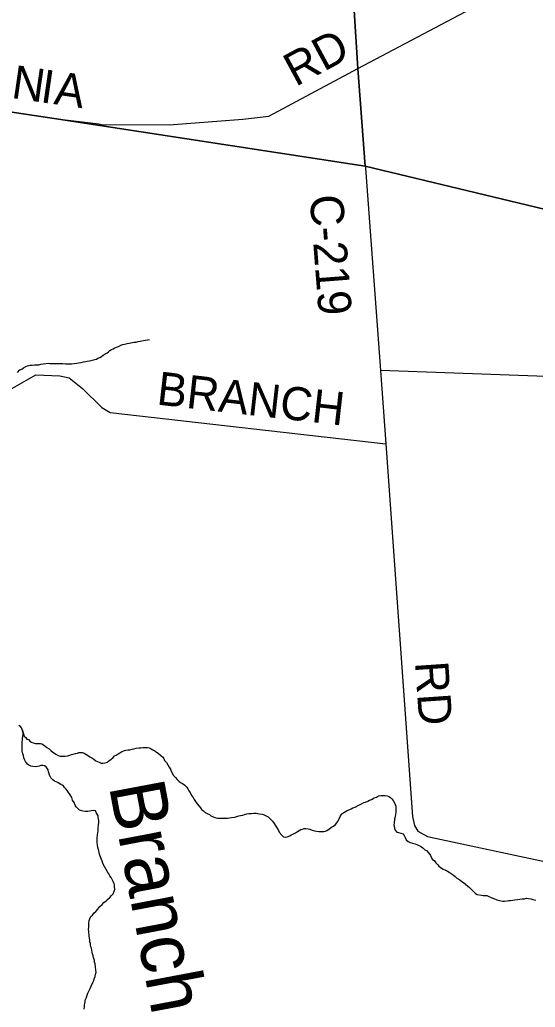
# Model space of a CAD drawing. Extents: x 0.4 to 34.4, y -2.1 to 19.9.
# Drawn here: x 4.522 to 5.402, y 15.102 to 16.79 of the extents above; entities that cross this region are included whole.
import ezdxf

# ---------------------------------------------------------------- set-up
doc = ezdxf.new("R2010")
doc.units = 0
for name, color, linetype in [('GM_X_County_Road', 7, 'Continuous'), ('GM_X_County_Road_Text', 7, 'Continuous'), ('GM_X_Minor_River', 7, 'Continuous'), ('GM_X_Minor_River_Text', 7, 'Continuous'), ('GM_X_Township', 7, 'Continuous'), ('GM_X_Township_Road', 7, 'Continuous')]:
    doc.layers.add(name, color=color, linetype=linetype)

msp = doc.modelspace()

# ---------------------------------------------------------------- linework, layer by layer
at = {"layer": 'GM_X_County_Road'}
for points in [[(5.0993, 16.7069), (5.2822, 16.8039), (5.7558, 17.055), (6.3625, 17.3767), (6.38, 17.386), (6.7247, 17.5708), (6.7542, 17.5855), (6.7786, 17.6112), (6.7991, 17.6537), (6.9135, 17.8219), (6.9221, 17.8335), (6.9343, 17.8393), (6.9503, 17.8402), (7.0217, 17.8445), (7.032, 17.8492), (7.2391, 18.0795)], [(4.6572, 16.6121), (4.6615, 16.6115), (4.7773, 16.6105), (4.9028, 16.6206), (4.9471, 16.6252), (5.0993, 16.7069)], [(5.0993, 16.7069), (5.1117, 16.5403), (5.112, 16.5365)], [(4.2994, 16.6582), (4.3075, 16.6628), (4.5805, 16.6217), (4.6572, 16.6121)], [(5.112, 16.5365), (5.1378, 16.1909), (5.1472, 16.0652)], [(4.0921, 16.025), (4.112, 16.0159), (4.1298, 16.0125), (4.1477, 16.0209), (4.1695, 16.03), (4.1937, 16.0409), (4.2276, 16.0516), (4.3098, 16.0801), (4.378, 16.119), (4.4038, 16.139), (4.4192, 16.1456), (4.4477, 16.1507), (4.4785, 16.1517), (4.5055, 16.158), (4.5496, 16.1834), (4.5902, 16.1818), (4.6065, 16.1781), (4.6289, 16.1599), (4.662, 16.1274), (4.6763, 16.1188), (5.1472, 16.0652)], [(5.1472, 16.0652), (5.1472, 16.0652), (5.1927, 15.4283), (5.1962, 15.413), (5.2017, 15.4034), (5.2182, 15.394), (5.4257, 15.3499), (5.4355, 15.3459), (5.4407, 15.3424), (5.4524, 15.2606), (5.4094, 15.0538), (5.3948, 14.9559)]]:
    msp.add_lwpolyline(points, dxfattribs=at)
at = {"layer": 'GM_X_Minor_River'}
for points in [[(4.6813, 16.2279), (4.6844, 16.2294), (4.6871, 16.2305), (4.6905, 16.232), (4.6944, 16.2338), (4.6978, 16.2352), (4.7009, 16.2359), (4.7055, 16.237), (4.7086, 16.2373), (4.7116, 16.238), (4.7143, 16.2384), (4.7174, 16.2391), (4.7208, 16.2394), (4.7239, 16.2401), (4.7277, 16.2408), (4.7304, 16.2415), (4.7335, 16.2422), (4.7361, 16.2425), (4.7403, 16.2432), (4.7434, 16.2435)], [(4.518, 16.1876), (4.5222, 16.1917), (4.5253, 16.1931), (4.5284, 16.1954), (4.5323, 16.1976), (4.5354, 16.199), (4.5396, 16.1997), (4.5434, 16.2), (4.5472, 16.2003), (4.551, 16.2006), (4.5545, 16.2006), (4.5579, 16.2013), (4.5621, 16.202), (4.5663, 16.2027), (4.5702, 16.203), (4.5728, 16.2029), (4.5763, 16.2028), (4.5793, 16.2028), (4.582, 16.2027), (4.5846, 16.2027), (4.5884, 16.2026), (4.593, 16.2025), (4.5957, 16.2025), (4.5999, 16.2024), (4.6033, 16.2024), (4.6071, 16.2023), (4.6106, 16.2022), (4.6148, 16.2029), (4.6193, 16.2032), (4.622, 16.2039), (4.6266, 16.2042), (4.6308, 16.2053), (4.6347, 16.206), (4.6373, 16.2067), (4.6412, 16.2074), (4.6454, 16.2084), (4.65, 16.2095), (4.6527, 16.2102), (4.6554, 16.2117), (4.6585, 16.2131), (4.6615, 16.2146), (4.6646, 16.2168), (4.6677, 16.2191), (4.6704, 16.2205), (4.6732, 16.2228), (4.6759, 16.225), (4.6786, 16.2265), (4.6813, 16.2279)], [(4.6839, 15.3082), (4.6836, 15.3109), (4.6829, 15.3135), (4.6815, 15.3174), (4.6793, 15.3216), (4.6778, 15.3243), (4.676, 15.327), (4.6741, 15.3301), (4.6723, 15.3328), (4.6693, 15.3378), (4.6671, 15.342), (4.6646, 15.347), (4.6624, 15.3523), (4.6603, 15.3577), (4.6592, 15.3604), (4.6581, 15.3638), (4.6574, 15.3669), (4.6564, 15.3719), (4.6553, 15.3753), (4.6546, 15.3791), (4.6544, 15.3837), (4.6541, 15.3879), (4.6542, 15.3921), (4.6546, 15.3966), (4.6551, 15.4008), (4.6556, 15.4035), (4.6556, 15.4061), (4.6561, 15.4088), (4.6565, 15.4137), (4.6567, 15.4187), (4.6567, 15.4213), (4.6561, 15.4267), (4.6558, 15.4293), (4.6543, 15.4324), (4.6525, 15.4355), (4.651, 15.4382), (4.6472, 15.4386), (4.6438, 15.4383), (4.6411, 15.4376), (4.638, 15.4369), (4.6342, 15.437), (4.6304, 15.4374), (4.6277, 15.4378), (4.624, 15.4394), (4.6206, 15.4429), (4.618, 15.4449), (4.6165, 15.4479), (4.6147, 15.4522), (4.6121, 15.4564), (4.6111, 15.4606), (4.6081, 15.4652), (4.6052, 15.4695), (4.6033, 15.4725), (4.6007, 15.4756), (4.5981, 15.478), (4.5959, 15.4814), (4.5921, 15.483), (4.5895, 15.4846), (4.5869, 15.4865), (4.5839, 15.4877), (4.5812, 15.4885), (4.5782, 15.4909), (4.5752, 15.4944), (4.5734, 15.4978), (4.572, 15.5013), (4.5713, 15.5047), (4.5702, 15.5082), (4.5669, 15.5135), (4.5643, 15.5151), (4.5612, 15.5155), (4.5578, 15.5156), (4.5551, 15.5145), (4.5524, 15.5138), (4.5486, 15.5131), (4.544, 15.5136), (4.541, 15.5144), (4.5376, 15.516), (4.535, 15.5179), (4.5316, 15.5222), (4.5305, 15.5249), (4.5291, 15.5287), (4.5281, 15.5329), (4.5274, 15.5356), (4.5263, 15.5405), (4.526, 15.5432), (4.5261, 15.5466), (4.5258, 15.5516), (4.5263, 15.5561), (4.5264, 15.5588), (4.5268, 15.5615), (4.5272, 15.5649), (4.5277, 15.5679), (4.5278, 15.5706), (4.5274, 15.5732), (4.526, 15.5771), (4.5249, 15.5798), (4.5231, 15.5825), (4.5204, 15.584)], [(4.526, 15.5771), (4.5292, 15.5656), (4.5322, 15.5633), (4.534, 15.5606), (4.5367, 15.5598), (4.5393, 15.5574), (4.5419, 15.5555), (4.5449, 15.5543), (4.5487, 15.5534), (4.5529, 15.553), (4.5571, 15.5529), (4.5598, 15.5525), (4.5624, 15.5509), (4.565, 15.5493), (4.5684, 15.5466), (4.5722, 15.5439), (4.5748, 15.5412), (4.5785, 15.5384), (4.5811, 15.5365), (4.5838, 15.5349), (4.5875, 15.5329), (4.5909, 15.5317), (4.5944, 15.5313), (4.597, 15.5313), (4.5997, 15.5316), (4.6039, 15.5323), (4.6077, 15.533), (4.6104, 15.5341), (4.6131, 15.5351), (4.617, 15.5362), (4.6204, 15.5369), (4.6231, 15.5376), (4.6258, 15.5376), (4.6284, 15.5375), (4.6322, 15.5367), (4.6349, 15.5351), (4.6379, 15.5335), (4.6416, 15.5304), (4.645, 15.5285), (4.6484, 15.5261), (4.6518, 15.5238), (4.6548, 15.5222), (4.6578, 15.521), (4.6612, 15.5198), (4.6639, 15.5198), (4.6673, 15.5201), (4.6715, 15.5215), (4.6743, 15.5234), (4.6774, 15.5256), (4.6812, 15.5293), (4.6836, 15.5323), (4.6867, 15.533), (4.6902, 15.5353), (4.6929, 15.5371), (4.6956, 15.539), (4.7006, 15.5412), (4.7033, 15.5419), (4.7071, 15.5422), (4.7101, 15.5425), (4.714, 15.5432), (4.717, 15.5443), (4.7209, 15.545), (4.7251, 15.5457), (4.7289, 15.546), (4.7323, 15.5463), (4.7362, 15.5466), (4.74, 15.5461), (4.743, 15.5457), (4.7464, 15.5441), (4.7494, 15.5425), (4.7528, 15.5406), (4.7554, 15.5386), (4.7584, 15.5367), (4.7629, 15.5328), (4.7655, 15.5301), (4.7678, 15.5274), (4.7692, 15.5243), (4.7726, 15.5208), (4.7748, 15.5166), (4.777, 15.5127), (4.7792, 15.5093), (4.7806, 15.5058), (4.7828, 15.502), (4.7839, 15.4993), (4.7876, 15.495), (4.7906, 15.4916), (4.7936, 15.4888), (4.7966, 15.4865), (4.7996, 15.4849), (4.8037, 15.4818), (4.8071, 15.4783), (4.8089, 15.4756), (4.8104, 15.4725), (4.813, 15.4695), (4.8152, 15.4645), (4.8181, 15.461), (4.8196, 15.4575), (4.8222, 15.4541), (4.8251, 15.4498), (4.8281, 15.4463), (4.8303, 15.4433)], [(4.8303, 15.4433), (4.8325, 15.4402), (4.8359, 15.4378), (4.8385, 15.4355), (4.8419, 15.4335), (4.8457, 15.4316), (4.8483, 15.4296), (4.8513, 15.4284), (4.8551, 15.4268), (4.8593, 15.4256), (4.8631, 15.4255), (4.8669, 15.4255), (4.8711, 15.4254), (4.8764, 15.4257), (4.8802, 15.426), (4.8837, 15.4267), (4.889, 15.4273), (4.8925, 15.4284), (4.896, 15.4295), (4.8986, 15.4302), (4.9029, 15.4309), (4.9055, 15.4316), (4.9098, 15.4327), (4.9128, 15.4334), (4.9174, 15.4337), (4.9216, 15.434), (4.9254, 15.4339), (4.9285, 15.4335), (4.9315, 15.433), (4.9357, 15.4322), (4.9391, 15.431), (4.9429, 15.4298), (4.9463, 15.4278), (4.9489, 15.4251), (4.9533, 15.4205), (4.9563, 15.4162), (4.9578, 15.4135), (4.9603, 15.4101), (4.9618, 15.4074), (4.9637, 15.4047), (4.9651, 15.4016), (4.9696, 15.3962), (4.9722, 15.3939), (4.9756, 15.393), (4.9787, 15.3937), (4.9829, 15.3952), (4.9856, 15.397), (4.9883, 15.3981), (4.9929, 15.4007), (4.9964, 15.4029), (5.0018, 15.4063), (5.0045, 15.407), (5.0076, 15.4077), (5.0102, 15.408), (5.0144, 15.4075), (5.0175, 15.4067), (5.0212, 15.4051), (5.025, 15.4039), (5.0288, 15.4031), (5.0326, 15.4026), (5.0372, 15.4026), (5.041, 15.4029), (5.0437, 15.4032), (5.0464, 15.4047), (5.0491, 15.4061), (5.0545, 15.4102), (5.0576, 15.4121), (5.0611, 15.4147), (5.0634, 15.4173), (5.0658, 15.4207), (5.0674, 15.4245), (5.069, 15.4282), (5.0718, 15.4331), (5.0753, 15.435), (5.0784, 15.4368), (5.0811, 15.4387), (5.0853, 15.4405), (5.088, 15.4416), (5.0907, 15.4431), (5.0946, 15.4445), (5.1, 15.4471), (5.103, 15.4489), (5.1057, 15.45), (5.1096, 15.4522), (5.1123, 15.4529), (5.1161, 15.4548), (5.1192, 15.4562), (5.1223, 15.4577), (5.1273, 15.4603), (5.1312, 15.4617), (5.1346, 15.4636), (5.1385, 15.4643), (5.1434, 15.4645), (5.1461, 15.4645), (5.1495, 15.4637), (5.1522, 15.4625), (5.1548, 15.4609), (5.1574, 15.4586), (5.1596, 15.4559), (5.1618, 15.452), (5.1629, 15.449)], [(5.1629, 15.449), (5.164, 15.4459), (5.1642, 15.4402), (5.1641, 15.4356), (5.1637, 15.4322), (5.1628, 15.4277), (5.162, 15.4239), (5.1611, 15.4178), (5.1606, 15.414), (5.162, 15.4083), (5.1631, 15.4048), (5.1657, 15.4017), (5.1687, 15.4009), (5.1725, 15.3997), (5.1763, 15.3985), (5.1789, 15.395), (5.1799, 15.3923), (5.1818, 15.3885), (5.1851, 15.3858), (5.1885, 15.3842), (5.1923, 15.383), (5.1972, 15.3814), (5.1999, 15.3806), (5.2033, 15.379), (5.2059, 15.3778), (5.2104, 15.375), (5.2138, 15.3715), (5.2164, 15.37), (5.2205, 15.3657), (5.2231, 15.3615), (5.226, 15.3557), (5.2298, 15.3526), (5.2324, 15.3491), (5.2357, 15.346), (5.2376, 15.3433), (5.2421, 15.3402), (5.2451, 15.3382), (5.2477, 15.3371), (5.2522, 15.3351), (5.2549, 15.3335), (5.2586, 15.3312), (5.262, 15.3288), (5.2654, 15.3257), (5.2684, 15.323), (5.2736, 15.3202), (5.2766, 15.3175), (5.2796, 15.3155), (5.283, 15.3128), (5.2871, 15.3093), (5.2901, 15.307), (5.2938, 15.3031), (5.2964, 15.3), (5.3002, 15.2969), (5.3028, 15.295), (5.3104, 15.2937), (5.3131, 15.2936), (5.3161, 15.2936), (5.3196, 15.2931), (5.323, 15.2919), (5.3256, 15.2907), (5.3282, 15.2895), (5.3313, 15.2883), (5.3366, 15.286), (5.3411, 15.2847), (5.3464, 15.2839), (5.3495, 15.2838), (5.354, 15.2841), (5.3571, 15.2848), (5.3598, 15.2848), (5.3636, 15.2855), (5.3674, 15.2858), (5.3716, 15.2865), (5.3755, 15.2868), (5.3797, 15.2875), (5.3835, 15.2878), (5.3873, 15.2885), (5.3907, 15.288), (5.3945, 15.2879), (5.3979, 15.2864), (5.4029, 15.2851)], [(4.632, 15.0991), (4.6325, 15.1036), (4.6325, 15.1063), (4.633, 15.1089), (4.6334, 15.1116), (4.6338, 15.1146), (4.6351, 15.118), (4.6363, 15.1211), (4.6383, 15.1264), (4.6399, 15.1301), (4.6419, 15.1343), (4.6439, 15.1384), (4.6467, 15.1448), (4.6483, 15.1479), (4.6491, 15.1509), (4.6508, 15.155), (4.6512, 15.1585), (4.6524, 15.1622), (4.6521, 15.1657), (4.6515, 15.1714), (4.6505, 15.1767), (4.6498, 15.1794), (4.6498, 15.1821), (4.648, 15.1871), (4.6473, 15.1901), (4.6463, 15.1936), (4.6456, 15.1966), (4.6449, 15.2001), (4.6442, 15.2031), (4.6435, 15.2058), (4.6428, 15.2089), (4.6425, 15.2115), (4.6418, 15.2142), (4.6415, 15.2169), (4.6408, 15.2211), (4.6405, 15.2237), (4.6405, 15.2264), (4.6398, 15.2291), (4.6399, 15.2317), (4.6396, 15.2356), (4.6397, 15.2386), (4.6397, 15.242), (4.6398, 15.2458), (4.6403, 15.2508), (4.6415, 15.2534), (4.6435, 15.2572), (4.6459, 15.2598), (4.649, 15.2635), (4.6517, 15.2662), (4.6552, 15.2699), (4.6588, 15.2744), (4.6627, 15.2781), (4.6654, 15.2811), (4.6693, 15.2845), (4.672, 15.2867), (4.6755, 15.2901), (4.6786, 15.2931), (4.6814, 15.2964), (4.6834, 15.3006), (4.6842, 15.304), (4.6839, 15.3082)]]:
    msp.add_lwpolyline(points, dxfattribs=at)
at = {"layer": 'GM_X_Township'}
for points in [[(3.9025, 16.8065), (3.923, 16.7452), (3.9228, 16.7376), (3.9173, 16.7229), (4.0113, 16.7086), (4.3075, 16.6628), (4.5805, 16.6217), (5.1117, 16.5403), (5.0993, 16.7069), (5.0712, 17.1497)], [(5.0712, 17.1497), (5.0993, 16.7069), (5.1117, 16.5403), (6.4528, 16.2176), (7.8323, 15.8856)], [(6.4528, 16.2176), (5.1117, 16.5403), (4.5805, 16.6217), (4.3075, 16.6628)]]:
    msp.add_lwpolyline(points, dxfattribs=at)
at = {"layer": 'GM_X_Township_Road'}
msp.add_lwpolyline([(6.4573, 16.1428), (5.1378, 16.1909)], dxfattribs=at)

# ---------------------------------------------------------------- texts
at = {"layer": 'GM_X_County_Road_Text'}
for s, height, rotation, p in [('RD', 0.05682, 28.3324, (4.9929, 16.6751)), ('N', 0.0568, 351.7434, (4.5061, 16.6568)), ('I', 0.0568, 351.7459, (4.5556, 16.6496)), ('A', 0.0568, 351.7427, (4.5787, 16.6463)), ('C-219', 0.05682, 274.4195, (5.0168, 16.4895)), ('BRANCH', 0.05682, 353.5323, (4.7544, 16.1327)), ('RD', 0.05682, 273.9467, (5.1967, 15.692))]:
    msp.add_text(s, height=height, rotation=rotation, dxfattribs=at).set_placement(p)
at = {"layer": 'GM_X_Minor_River_Text'}
msp.add_text('Branch', height=0.09472, rotation=280.7121, dxfattribs=at).set_placement((4.6739, 15.4807))

doc.saveas('drawing.dxf')
